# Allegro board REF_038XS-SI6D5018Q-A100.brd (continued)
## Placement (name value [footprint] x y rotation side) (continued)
NOREF#1785  -  []  347.56 144.79 90 top
NOREF#1786  -  []  270.24 240.08 0 top
NOREF#1787  -  []  307.77 233.98 0 top
NOREF#1788  -  []  233.34 210 0 top
NOREF#1789  -  []  228.23 182.08 90 top
NOREF#1790  -  []  274.44 141.43 0 top
NOREF#1791  -  []  270.73 166.09 0 top
NOREF#1792  -  []  485.78 195.82 90 top
NOREF#1793  -  []  82.32 289.93 90 top
NOREF#1794  -  []  348.93 240.74 90 top
NOREF#1795  -  []  311.69 269.1 0 top
NOREF#1796  -  []  307.58 238.18 90 top
NOREF#1797  -  []  450.05 158.1 0 top
NOREF#1798  -  []  210.56 175.55 90 top
NOREF#1799  -  []  331.64 182.3 90 top
NOREF#1800  -  []  334.36 241.55 0 top
NOREF#1801  -  []  232.23 170.19 90 top
NOREF#1802  -  []  335.58 254.86 90 top
NOREF#1803  -  []  286.56 295.33 90 top
NOREF#1804  -  []  210.56 252.32 0 top
NOREF#1805  -  []  273.11 190.18 90 top
NOREF#1806  -  []  100.39 186.2 0 top
NOREF#1807  -  []  271.8 250.18 90 top
NOREF#1808  -  []  475.18 133.72 90 top
NOREF#1809  -  []  242.56 269.73 0 top
NOREF#1810  -  []  254.36 241.55 0 top
NOREF#1811  -  []  285.1 268.22 0 top
NOREF#1812  -  []  265.96 188.86 0 top
NOREF#1813  -  []  356.29 269.73 0 top
NOREF#1814  -  []  110.89 154.45 0 top
NOREF#1815  -  []  122.18 172.97 0 top
NOREF#1816  -  []  212.78 239.12 90 top
NOREF#1817  -  []  347.9 178.48 90 top
NOREF#1818  -  []  243.54 207.24 90 top
NOREF#1819  -  []  90.88 200.91 90 top
NOREF#1820  -  []  254.31 242 90 top
NOREF#1821  -  []  262.63 289.44 0 top
NOREF#1822  -  []  480.6 158.1 0 top
NOREF#1823  -  []  292.96 183.2 0 top
NOREF#1824  -  []  87.69 186.2 0 top
NOREF#1825  -  []  351.08 269.73 0 top
NOREF#1826  -  []  480.05 156.45 0 top
NOREF#1827  -  []  557.76 164.1 90 top
NOREF#1828  -  []  291.33 267.13 0 top
NOREF#1829  -  []  268.25 234.12 90 top
NOREF#1830  -  []  293.39 243.61 0 top
NOREF#1831  -  []  223.09 174.38 0 top
NOREF#1832  -  []  557.76 167.08 0 top
NOREF#1833  -  []  295.16 239.65 90 top
NOREF#1834  -  []  214.36 183.2 0 top
NOREF#1835  -  []  260.33 249.91 0 top
NOREF#1836  -  []  456.32 276.81 90 top
NOREF#1837  -  []  232.79 251.08 0 top
NOREF#1838  -  []  272.23 227.99 0 top
NOREF#1839  -  []  271.54 186.58 0 top
NOREF#1840  -  []  335.01 253.56 90 top
NOREF#1841  -  []  476.65 217.95 0 top
NOREF#1842  -  []  83.29 154.45 0 top
NOREF#1843  -  []  362.64 267.56 0 top
NOREF#1844  -  []  455.4 217.95 0 top
NOREF#1845  -  []  306.06 148.23 0 top
NOREF#1846  -  []  533.93 206.42 0 top
NOREF#1847  -  []  459.8 217.95 0 top
NOREF#1848  -  []  535.51 221.15 90 top
NOREF#1849  -  []  232.46 190.18 90 top
NOREF#1850  -  []  314.91 223.58 90 top
NOREF#1851  -  []  116.75 165.57 90 top
NOREF#1852  -  []  350.54 240.4 0 top
NOREF#1853  -  []  474.45 249.7 0 top
NOREF#1854  -  []  355.37 249.88 90 top
NOREF#1855  -  []  253.09 183.29 90 top
NOREF#1856  -  []  280.81 158.16 0 top
NOREF#1857  -  []  230.91 247.23 90 top
NOREF#1858  -  []  121.88 139.01 0 top
NOREF#1859  -  []  295.58 243.29 90 top
NOREF#1860  -  []  310.55 134.62 90 top
NOREF#1861  -  []  314.73 251.08 0 top
NOREF#1862  -  []  267.56 144.79 0 top
NOREF#1863  -  []  287.56 272.93 0 top
NOREF#1864  -  []  234.61 295.18 90 top
NOREF#1865  -  []  115.04 217.95 0 top
NOREF#1866  -  []  332.66 242 90 top
NOREF#1867  -  []  113.09 217.95 0 top
NOREF#1868  -  []  305.95 248.85 0 top
NOREF#1869  -  []  308.25 233.12 90 top
NOREF#1870  -  []  570 166.3 90 top
NOREF#1871  -  []  225.55 234.13 90 top
NOREF#1872  -  []  254.31 253.56 90 top
NOREF#1873  -  []  290.61 247.17 90 top
NOREF#1874  -  []  307.25 238.48 90 top
NOREF#1875  -  []  333.66 194.76 0 top
NOREF#1876  -  []  456.55 177.57 0 top
NOREF#1877  -  []  570 147.59 90 top
NOREF#1878  -  []  214.66 241.23 0 top
NOREF#1879  -  []  353.66 209.1 90 top
NOREF#1880  -  []  232.74 184.64 90 top
NOREF#1881  -  []  449.05 154.45 0 top
NOREF#1882  -  []  267.9 242.38 90 top
NOREF#1883  -  []  450.05 253.35 0 top
NOREF#1884  -  []  456.64 232.66 0 top
NOREF#1885  -  []  310.83 244.63 0 top
NOREF#1886  -  []  313.66 269.1 90 top
NOREF#1887  -  []  316.94 252.76 90 top
NOREF#1888  -  []  305.05 145.8 0 top
NOREF#1889  -  []  121.88 205.05 0 top
NOREF#1890  -  []  282.34 207.24 0 top
NOREF#1891  -  []  364.49 208.86 0 top
NOREF#1892  -  []  253.99 182.3 90 top
NOREF#1893  -  []  242.24 135.78 90 top
NOREF#1894  -  []  351.54 185.94 90 top
NOREF#1895  -  []  332.01 243.2 0 top
NOREF#1896  -  []  225.06 226.14 0 top
NOREF#1897  -  []  467.84 170.11 90 top
NOREF#1898  -  []  253.99 193.86 90 top
NOREF#1899  -  []  346.92 249.88 90 top
NOREF#1900  -  []  309.83 209.1 90 top
NOREF#1901  -  []  231.49 240.02 0 top
NOREF#1902  -  []  216.33 14.86 90 top
NOREF#1903  -  []  211.16 236.15 90 top
NOREF#1904  -  []  227.59 183.28 0 top
NOREF#1905  -  []  97.24 151.25 90 top
NOREF#1906  -  []  223.27 234.06 0 top
NOREF#1907  -  []  250.56 187.12 90 top
NOREF#1908  -  []  350.24 245.28 0 top
NOREF#1909  -  []  316.65 267.92 0 top
NOREF#1910  -  []  310.54 180.4 0 top
NOREF#1911  -  []  263.27 174.62 0 top
NOREF#1912  -  []  232.46 180.42 90 top
NOREF#1913  -  []  228.27 185.28 0 top
NOREF#1914  -  []  263.71 291.06 0 top
NOREF#1915  -  []  346.93 178.18 90 top
NOREF#1916  -  []  235.38 189.88 90 top
NOREF#1917  -  []  273.63 138.2 0 top
NOREF#1918  -  []  313.11 190.18 90 top
NOREF#1919  -  []  270.89 243.32 0 top
NOREF#1920  -  []  302.22 288.34 90 top
NOREF#1921  -  []  270.5 183.67 90 top
NOREF#1922  -  []  292.01 243.2 0 top
NOREF#1923  -  []  274.91 163.58 0 top
NOREF#1924  -  []  293.39 195.18 0 top
NOREF#1925  -  []  271.19 209.1 90 top
NOREF#1926  -  []  456.4 189.85 0 top
NOREF#1927  -  []  264.52 281.35 90 top
NOREF#1928  -  []  271.19 269.1 90 top
NOREF#1929  -  []  360.04 135.47 90 top
NOREF#1930  -  []  90.64 221.6 0 top
NOREF#1931  -  []  547.34 235.63 0 top
NOREF#1932  -  []  474.25 158.1 0 top
NOREF#1933  -  []  487.64 201.86 90 top
NOREF#1934  -  []  325.29 212.67 0 top
NOREF#1935  -  []  315.44 254.76 90 top
NOREF#1936  -  []  351.15 183.67 90 top
NOREF#1937  -  []  81.69 288.47 90 top
NOREF#1938  -  []  362.34 207.24 0 top
NOREF#1939  -  []  227.05 134.31 90 top
NOREF#1940  -  []  350.57 268.63 0 top
NOREF#1941  -  []  349.59 246.58 0 top
NOREF#1942  -  []  277.95 143.53 90 top
NOREF#1943  -  []  83.67 262.04 90 top
NOREF#1944  -  []  232.14 240.12 90 top
NOREF#1945  -  []  213.1 238.82 90 top
NOREF#1946  -  []  449.05 217.95 0 top
NOREF#1947  -  []  560.13 154.99 0 top
NOREF#1948  -  []  363.24 208.22 90 top
NOREF#1949  -  []  278.32 142.99 0 top
NOREF#1950  -  []  351.54 245.93 90 top
NOREF#1951  -  []  454.65 156.45 0 top
NOREF#1952  -  []  309.85 244.32 90 top
NOREF#1953  -  []  40.05 272.89 0 top
NOREF#1954  -  []  229.59 185.93 0 top
NOREF#1955  -  []  347.58 183.28 0 top
NOREF#1956  -  []  340.66 226.14 0 top
NOREF#1957  -  []  38.35 142.86 0 top
NOREF#1958  -  []  302.63 289.44 0 top
NOREF#1959  -  []  267.25 173.9 90 top
NOREF#1960  -  []  102.38 202.18 0 top
NOREF#1961  -  []  302.86 166.14 0 top
NOREF#1962  -  []  344.52 283.89 90 top
NOREF#1963  -  []  113.09 186.2 0 top
NOREF#1964  -  []  232.46 241.7 0 top
NOREF#1965  -  []  282.56 209.73 0 top
NOREF#1966  -  []  270.57 208.63 0 top
NOREF#1967  -  []  243.54 267.24 90 top
NOREF#1968  -  []  311.16 183.67 90 top
NOREF#1969  -  []  324.79 211.56 0 top
NOREF#1970  -  []  304.96 134.08 0 top
NOREF#1971  -  []  244.35 211.05 90 top
NOREF#1972  -  []  454.65 251.7 0 top
NOREF#1973  -  []  212.66 253.56 90 top
NOREF#1974  -  []  301.62 289.14 90 top
NOREF#1975  -  []  534.23 206.74 0 top
NOREF#1976  -  []  348.23 178.18 90 top
NOREF#1977  -  []  251.64 243.61 0 top
NOREF#1978  -  []  55.09 268.86 0 top
NOREF#1979  -  []  350.73 166.09 90 top
NOREF#1980  -  []  268.27 184.64 90 top
NOREF#1981  -  []  463 214.75 90 top
NOREF#1982  -  []  472.5 154.45 0 top
NOREF#1983  -  []  312.14 180.12 0 top
NOREF#1984  -  []  546.96 196.64 0 top
NOREF#1985  -  []  121.88 236.8 0 top
NOREF#1986  -  []  309.89 246.26 0 top
NOREF#1987  -  []  352.23 227.99 90 top
NOREF#1988  -  []  285.29 212.67 0 top
NOREF#1989  -  []  228.93 240.73 0 top
NOREF#1990  -  []  348.93 208.11 0 top
NOREF#1991  -  []  289.83 263.63 90 top
NOREF#1992  -  []  211.31 194.76 0 top
NOREF#1993  -  []  236.97 208.22 90 top
NOREF#1994  -  []  239.44 140.92 0 top
NOREF#1995  -  []  486.4 219.95 0 top
NOREF#1996  -  []  236.97 268.22 90 top
NOREF#1997  -  []  325.83 169.63 90 top
NOREF#1998  -  []  89.64 154.45 0 top
NOREF#1999  -  []  180.33 2.28 90 top
NOREF#2000  -  []  312.23 170.19 90 top
NOREF#2001  -  []  478.85 154.45 0 top
NOREF#2002  -  []  220.33 249.91 0 top
NOREF#2003  -  []  320.04 135.47 90 top
NOREF#2004  -  []  229.83 209.1 90 top
NOREF#2005  -  []  229.89 246.91 0 top
NOREF#2006  -  []  272.79 183.41 90 top
NOREF#2007  -  []  323.37 273.06 90 top
NOREF#2008  -  []  240.81 218.66 90 top
NOREF#2009  -  []  285.9 272.03 0 top
NOREF#2010  -  []  295.16 191.22 90 top
NOREF#2011  -  []  213.61 253.56 90 top
NOREF#2012  -  []  224.42 175.77 0 top
NOREF#2013  -  []  225.96 188.86 90 top
NOREF#2014  -  []  226.97 246.58 0 top
NOREF#2015  -  []  350.18 191.08 0 top
NOREF#2016  -  []  243.98 207.75 90 top
NOREF#2017  -  []  227.75 235.77 0 top
NOREF#2018  -  []  267.58 238.18 0 top
NOREF#2019  -  []  213.22 178.82 90 top
NOREF#2020  -  []  239.72 136.37 0 top
NOREF#2021  -  []  303.09 234.94 0 top
NOREF#2022  -  []  481.8 221.6 0 top
NOREF#2023  -  []  283.37 213.06 90 top
NOREF#2024  -  []  251.64 183.61 0 top
NOREF#2025  -  []  305.06 166.14 0 top
NOREF#2026  -  []  461 212.35 0 top
NOREF#2027  -  []  225.44 146.16 90 top
NOREF#2028  -  []  286.56 297.26 90 top
NOREF#2029  -  []  309.53 178.82 0 top
NOREF#2030  -  []  102.08 236.8 0 top
NOREF#2031  -  []  333.22 180.02 0 top
NOREF#2032  -  []  214.68 243.61 0 top
NOREF#2033  -  []  270.19 238.82 90 top
NOREF#2034  -  []  546.66 209.66 0 top
NOREF#2035  -  []  310.24 245.28 0 top
NOREF#2036  -  []  292.54 194.86 90 top
NOREF#2037  -  []  49.74 249.91 90 top
NOREF#2038  -  []  456.64 137.41 0 top
NOREF#2039  -  []  102.14 158.1 0 top
NOREF#2040  -  []  211.64 193.86 90 top
NOREF#2041  -  []  95.24 251.7 0 top
NOREF#2042  -  []  37.31 268.86 0 top
NOREF#2043  -  []  481.8 158.1 0 top
NOREF#2044  -  []  474.45 217.95 0 top
NOREF#2045  -  []  78.8 277.9 0 top
NOREF#2046  -  []  253.29 193.86 90 top
NOREF#2047  -  []  297.83 211.13 0 top
NOREF#2048  -  []  292.45 250.39 0 top
NOREF#2049  -  []  468.14 236.47 0 top
NOREF#2050  -  []  317.71 207.75 90 top
NOREF#2051  -  []  282.91 267.92 90 top
NOREF#2052  -  []  354.73 251.08 0 top
NOREF#2053  -  []  485.2 154.45 0 top
NOREF#2054  -  []  305.33 135.72 0 top
NOREF#2055  -  []  323.24 268.22 90 top
NOREF#2056  -  []  456 279.03 90 top
NOREF#2057  -  []  327.4 267.92 90 top
NOREF#2058  -  []  114.29 156.45 0 top
NOREF#2059  -  []  272.13 181.42 90 top
NOREF#2060  -  []  80.94 278.6 0 top
NOREF#2061  -  []  313.4 295.57 0 top
NOREF#2062  -  []  255.83 259.63 0 top
NOREF#2063  -  []  330.56 180.75 0 top
NOREF#2064  -  []  231.16 181.72 90 top
NOREF#2065  -  []  324.79 271.56 0 top
NOREF#2066  -  []  541.25 148.37 0 top
NOREF#2067  -  []  250.61 187.17 90 top
NOREF#2068  -  []  270.5 190.18 90 top
NOREF#2069  -  []  353.4 295.57 0 top
NOREF#2070  -  []  305.88 235.27 0 top
NOREF#2071  -  []  474.45 154.45 0 top
NOREF#2072  -  []  230.5 181.72 90 top
NOREF#2073  -  []  304.52 283.89 90 top
NOREF#2074  -  []  330.56 247.12 90 top
NOREF#2075  -  []  317.14 144.1 90 top
NOREF#2076  -  []  345.48 173.73 90 top
NOREF#2077  -  []  283.15 211.05 0 top
NOREF#2078  -  []  547.04 225.79 0 top
NOREF#2079  -  []  343.27 234.62 0 top
NOREF#2080  -  []  291.96 253.56 90 top
NOREF#2081  -  []  309.53 178.82 90 top
NOREF#2082  -  []  341.62 289.14 90 top
NOREF#2083  -  []  449.05 154.45 0 top
NOREF#2084  -  []  213.22 180.02 0 top
NOREF#2085  -  []  349.59 245.29 90 top
NOREF#2086  -  []  293.54 179.12 90 top
NOREF#2087  -  []  467.84 204.4 90 top
NOREF#2088  -  []  263.27 235.18 0 top
NOREF#2089  -  []  347.77 174.98 0 top
NOREF#2090  -  []  331.34 194.86 0 top
NOREF#2091  -  []  314.78 182.68 0 top
NOREF#2092  -  []  90.79 132.82 0 top
NOREF#2093  -  []  270.57 268.63 90 top
NOREF#2094  -  []  343.71 283.32 90 top
NOREF#2095  -  []  79.1 264.51 0 top
NOREF#2096  -  []  273.66 269.1 90 top
NOREF#2097  -  []  347.94 241.05 0 top
NOREF#2098  -  []  226.29 191.08 0 top
NOREF#2099  -  []  115.04 249.7 0 top
NOREF#2100  -  []  323.98 267.75 90 top
NOREF#2101  -  []  539.45 206.74 90 top
NOREF#2102  -  []  48.35 268.47 0 top
NOREF#2103  -  []  349.23 268.44 0 top
NOREF#2104  -  []  351.48 180.02 0 top
NOREF#2105  -  []  214.36 254.76 0 top
NOREF#2106  -  []  342.22 288.34 90 top
NOREF#2107  -  []  305.48 233.73 90 top
NOREF#2108  -  []  119.44 186.2 0 top
NOREF#2109  -  []  468.14 138.68 0 top
NOREF#2110  -  []  534.23 208.14 0 top
NOREF#2111  -  []  289.83 203.63 90 top
NOREF#2112  -  []  310.57 268.63 90 top
NOREF#2113  -  []  267.64 181.38 0 top
NOREF#2114  -  []  45.61 272.5 0 top
NOREF#2115  -  []  478.85 217.95 0 top
NOREF#2116  -  []  228.01 233.3 90 top
NOREF#2117  -  []  291.34 243.29 0 top
NOREF#2118  -  []  223.09 173.82 0 top
NOREF#2119  -  []  276.97 208.22 90 top
NOREF#2120  -  []  295.71 253.56 90 top
NOREF#2121  -  []  214.68 183.61 0 top
NOREF#2122  -  []  220.66 226.14 0 top
NOREF#2123  -  []  278.83 268.22 0 top
NOREF#2124  -  []  357.14 138.77 90 top
NOREF#2125  -  []  230.84 183.37 0 top
NOREF#2126  -  []  316.07 267.24 0 top
NOREF#2127  -  []  251.16 176.15 90 top
NOREF#2128  -  []  242.57 160.09 0 top
NOREF#2129  -  []  109.42 133.72 90 top
NOREF#2130  -  []  79.1 278.23 0 top
NOREF#2131  -  []  535.51 234.1 90 top
NOREF#2132  -  []  318.39 139.82 90 top
NOREF#2133  -  []  269.59 245.93 90 top
NOREF#2134  -  []  485.2 186.2 0 top
NOREF#2135  -  []  276.47 209.49 0 top
NOREF#2136  -  []  310.82 189.88 90 top
NOREF#2137  -  []  304.96 135.09 0 top
NOREF#2138  -  []  236.23 134 90 top
NOREF#2139  -  []  310.51 239.12 90 top
NOREF#2140  -  []  226.94 238.18 90 top
NOREF#2141  -  []  83.29 249.7 0 top
NOREF#2142  -  []  229.89 246.26 0 top
NOREF#2143  -  []  337.83 271.13 0 top
NOREF#2144  -  []  358.33 268.22 90 top
NOREF#2145  -  []  272.79 191.08 0 top
NOREF#2146  -  []  109.94 246.5 90 top
NOREF#2147  -  []  229.15 210.51 0 top
NOREF#2148  -  []  229.89 185.61 0 top
NOREF#2149  -  []  348.93 181.38 0 top
NOREF#2150  -  []  245.83 229.63 90 top
NOREF#2151  -  []  475.45 221.6 0 top
NOREF#2152  -  []  325.4 272.03 90 top
NOREF#2153  -  []  102.38 233.93 0 top
NOREF#2154  -  []  266.93 238.18 90 top
NOREF#2155  -  []  359.44 136.62 90 top
NOREF#2156  -  []  310.55 134.62 0 top
NOREF#2157  -  []  308.25 234.12 90 top
NOREF#2158  -  []  473.7 251.7 0 top
NOREF#2159  -  []  456.4 253.35 0 top
NOREF#2160  -  []  362.91 267.92 0 top
NOREF#2161  -  []  303.27 234.06 0 top
NOREF#2162  -  []  233.03 294.95 0 top
NOREF#2163  -  []  291.64 183.61 0 top
NOREF#2164  -  []  307.9 178.48 90 top
NOREF#2165  -  []  259.87 207.91 0 top
NOREF#2166  -  []  265.98 245.61 0 top
NOREF#2167  -  []  225.43 295.26 0 top
NOREF#2168  -  []  88.89 188.2 0 top
NOREF#2169  -  []  356.65 207.92 0 top
NOREF#2170  -  []  355.98 182.68 90 top
NOREF#2171  -  []  236.47 209.49 0 top
NOREF#2172  -  []  348.27 185.93 0 top
NOREF#2173  -  []  272.13 243.4 90 top
NOREF#2174  -  []  352.13 240.12 0 top
NOREF#2175  -  []  295.41 295.7 90 top
NOREF#2176  -  []  324.68 274.19 0 top
NOREF#2177  -  []  333.99 193.86 90 top
NOREF#2178  -  []  303.27 174.62 0 top
NOREF#2179  -  []  477.18 160.47 0 top
NOREF#2180  -  []  107.94 148.85 0 top
NOREF#2181  -  []  348.01 173.3 90 top
NOREF#2182  -  []  310.89 183.33 0 top
NOREF#2183  -  []  293.54 190.69 90 top
NOREF#2184  -  []  251.16 191.72 0 top
NOREF#2185  -  []  266.93 189.88 90 top
NOREF#2186  -  []  236.07 207.24 0 top
NOREF#2187  -  []  363.54 207.24 90 top
NOREF#2188  -  []  304.52 290.49 0 top
NOREF#2189  -  []  90.88 202.18 90 top
NOREF#2190  -  []  267.93 247.56 0 top
NOREF#2191  -  []  270.91 187.24 90 top
NOREF#2192  -  []  540.55 206.94 0 top
NOREF#2193  -  []  101.59 180.6 0 top
NOREF#2194  -  []  345.48 233.73 90 top
NOREF#2195  -  []  459.8 249.7 0 top
NOREF#2196  -  []  37.31 266.66 0 top
NOREF#2197  -  []  291.83 170.23 315 top
NOREF#2198  -  []  213.54 190.69 90 top
NOREF#2199  -  []  480.18 202.82 0 top
NOREF#2200  -  []  309.23 240.41 0 top
NOREF#2201  -  []  268.17 137.2 90 top
NOREF#2202  -  []  487.64 138.36 90 top
NOREF#2203  -  []  339.41 166.69 0 top
NOREF#2204  -  []  114.84 189.85 0 top
NOREF#2205  -  []  272.14 240.12 90 top
NOREF#2206  -  []  232.13 183.41 90 top
NOREF#2207  -  []  80 291.62 90 top
NOREF#2208  -  []  121.88 170.11 90 top
NOREF#2209  -  []  268.66 226.14 0 top
NOREF#2210  -  []  350.18 243.37 0 top
NOREF#2211  -  []  108.69 249.7 0 top
NOREF#2212  -  []  270.51 179.12 90 top
NOREF#2213  -  []  308.27 184.64 90 top
NOREF#2214  -  []  310.91 187.24 90 top
NOREF#2215  -  []  294.36 254.76 0 top
NOREF#2216  -  []  541.25 167.08 0 top
NOREF#2217  -  []  294.68 195.18 0 top
NOREF#2218  -  []  456.4 221.6 0 top
NOREF#2219  -  []  293.09 255.5 0 top
NOREF#2220  -  []  315.98 182.68 90 top
NOREF#2221  -  []  293.22 251.59 0 top
NOREF#2222  -  []  219.12 288.34 0 top
NOREF#2223  -  []  240.04 140.12 0 top
NOREF#2224  -  []  355.05 190.18 90 top
NOREF#2225  -  []  315.38 189.88 90 top
NOREF#2226  -  []  459.8 154.45 0 top
NOREF#2227  -  []  232.06 185.29 90 top
NOREF#2228  -  []  549.91 171.11 0 top
NOREF#2229  -  []  233.63 138.2 0 top
NOREF#2230  -  []  107.94 188.2 0 top
NOREF#2231  -  []  114.84 221.6 0 top
NOREF#2232  -  []  470.3 186.2 0 top
NOREF#2233  -  []  271.16 185.61 0 top
NOREF#2234  -  []  357.71 207.75 90 top
NOREF#2235  -  []  354.91 223.58 90 top
NOREF#2236  -  []  350.83 183.37 90 top
NOREF#2237  -  []  268.01 174.3 90 top
NOREF#2238  -  []  332.45 178.82 0 top
NOREF#2239  -  []  95.24 188.2 0 top
NOREF#2240  -  []  478.18 232.07 0 top
NOREF#2241  -  []  351.48 241.42 90 top
NOREF#2242  -  []  487.64 139.01 0 top
NOREF#2243  -  []  534.61 218.68 0 top
NOREF#2244  -  []  480.8 154.45 0 top
NOREF#2245  -  []  263.27 174.06 0 top
NOREF#2246  -  []  362.56 209.73 0 top
NOREF#2247  -  []  255.58 254.86 90 top
NOREF#2248  -  []  245.4 272.03 90 top
NOREF#2249  -  []  482.05 246.5 90 top
NOREF#2250  -  []  230.13 268.11 90 top
NOREF#2251  -  []  305.68 245.29 90 top
NOREF#2252  -  []  352.13 183.41 0 top
NOREF#2253  -  []  310.91 247.88 0 top
NOREF#2254  -  []  292.78 190.69 90 top
NOREF#2255  -  []  268.27 245.28 0 top
NOREF#2256  -  []  102.08 172.65 90 top
NOREF#2257  -  []  364.35 271.05 90 top
NOREF#2258  -  []  264.09 171.46 90 top
NOREF#2259  -  []  487.64 141.55 0 top
NOREF#2260  -  []  475.18 133.72 0 top
NOREF#2261  -  []  310.86 185.29 0 top
NOREF#2262  -  []  366.03 274.19 0 top
NOREF#2263  -  []  308.93 268.11 0 top
NOREF#2264  -  []  330.61 175.6 90 top
NOREF#2265  -  []  228.25 174.12 90 top
NOREF#2266  -  []  227.63 187.24 90 top
NOREF#2267  -  []  283.54 267.24 90 top
NOREF#2268  -  []  230.84 238.82 0 top
NOREF#2269  -  []  316.89 133.69 0 top
NOREF#2270  -  []  358.33 208.22 90 top
NOREF#2271  -  []  543.98 171.11 0 top
NOREF#2272  -  []  456.55 177.57 0 top
NOREF#2273  -  []  80.47 265.74 0 top
NOREF#2274  -  []  303.09 172.9 0 top
NOREF#2275  -  []  292.54 254.86 90 top
NOREF#2276  -  []  89.64 186.2 0 top
NOREF#2277  -  []  345.33 135.72 0 top
NOREF#2278  -  []  272.23 167.99 0 top
NOREF#2279  -  []  313.76 183.65 0 top
NOREF#2280  -  []  541.25 164.88 0 top
NOREF#2281  -  []  65.76 265.88 0 top
NOREF#2282  -  []  306.92 249.88 90 top
NOREF#2283  -  []  343.95 172.9 90 top
NOREF#2284  -  []  311.16 243.67 90 top
NOREF#2285  -  []  230.73 226.09 90 top
NOREF#2286  -  []  230.83 191.08 0 top
NOREF#2287  -  []  266.45 147.01 90 top
NOREF#2288  -  []  57.83 272.89 0 top
NOREF#2289  -  []  307.94 181.06 0 top
NOREF#2290  -  []  311.48 251.08 0 top
NOREF#2291  -  []  349.33 270.27 0 top
NOREF#2292  -  []  480.05 219.95 0 top
NOREF#2293  -  []  498.93 206.36 0 top
NOREF#2294  -  []  226.29 251.08 0 top
NOREF#2295  -  []  486.95 158.1 0 top
NOREF#2296  -  []  251.34 254.86 0 top
NOREF#2297  -  []  214.31 193.56 90 top
NOREF#2298  -  []  349.15 210.51 0 top
NOREF#2299  -  []  315.44 194.76 90 top
NOREF#2300  -  []  226.94 238.18 0 top
NOREF#2301  -  []  255.56 252.47 90 top
NOREF#2302  -  []  350.24 180.08 0 top
NOREF#2303  -  []  286.75 269.12 0 top
NOREF#2304  -  []  312.78 243.4 0 top
NOREF#2305  -  []  345.95 188.86 90 top
NOREF#2306  -  []  272.13 243.4 0 top
NOREF#2307  -  []  227.41 133.69 0 top
NOREF#2308  -  []  309.23 241.06 0 top
NOREF#2309  -  []  267.64 182.03 0 top
NOREF#2310  -  []  224.42 235.77 0 top
NOREF#2311  -  []  365.1 268.22 0 top
NOREF#2312  -  []  345.95 248.85 90 top
NOREF#2313  -  []  227.94 181.06 0 top
NOREF#2314  -  []  64.97 272.5 90 top
NOREF#2315  -  []  79.1 276.97 0 top
NOREF#2316  -  []  229.5 208.8 90 top
NOREF#2317  -  []  535.13 206.42 90 top
NOREF#2318  -  []  350.57 208.63 90 top
NOREF#2319  -  []  478.85 249.7 0 top
NOREF#2320  -  []  308.01 233.3 90 top
NOREF#2321  -  []  543.98 154.6 0 top
NOREF#2322  -  []  467.84 236.15 90 top
NOREF#2323  -  []  456.55 209.32 0 top
NOREF#2324  -  []  294.38 183.29 0 top
NOREF#2325  -  []  310.5 243.67 90 top
NOREF#2326  -  []  360.81 158.16 90 top
NOREF#2327  -  []  259.87 267.91 0 top
NOREF#2328  -  []  84.1 277.6 0 top
NOREF#2329  -  []  316.11 234.13 90 top
NOREF#2330  -  []  307.25 233.9 90 top
NOREF#2331  -  []  255.38 253.86 90 top
NOREF#2332  -  []  95.79 221.6 0 top
NOREF#2333  -  []  230.84 182.62 0 top
NOREF#2334  -  []  498.93 225.77 0 top
NOREF#2335  -  []  268.25 233.12 90 top
NOREF#2336  -  []  83.8 291.64 0 top
NOREF#2337  -  []  227.85 138.1 0 top
NOREF#2338  -  []  253.54 179.12 90 top
NOREF#2339  -  []  226.91 144.24 0 top
NOREF#2340  -  []  299.41 166.69 0 top
NOREF#2341  -  []  351.15 239.12 90 top
NOREF#2342  -  []  238.32 141.41 90 top
NOREF#2343  -  []  323.55 213.3 0 top
NOREF#2344  -  []  286.24 294.36 0 top
NOREF#2345  -  []  226.54 134.31 90 top
NOREF#2346  -  []  353.1 190.18 90 top
NOREF#2347  -  []  351.15 246.26 90 top
NOREF#2348  -  []  265.33 133.69 0 top
NOREF#2349  -  []  78.8 264.19 0 top
NOREF#2350  -  []  267.05 133.3 90 top
NOREF#2351  -  []  333.09 194.86 90 top
NOREF#2352  -  []  560.13 154.21 90 top
NOREF#2353  -  []  229.23 181.06 0 top
NOREF#2354  -  []  457.49 273.15 0 top
NOREF#2355  -  []  267.64 241.38 90 top
NOREF#2356  -  []  235.98 242.68 90 top
NOREF#2357  -  []  317.95 140.86 90 top
NOREF#2358  -  []  211.16 180.15 0 top
NOREF#2359  -  []  307.94 241.7 0 top
NOREF#2360  -  []  268.25 173.12 90 top
NOREF#2361  -  []  311.48 181.42 90 top
NOREF#2362  -  []  284.68 274.19 0 top
NOREF#2363  -  []  480.8 186.2 0 top
NOREF#2364  -  []  233.4 295.57 0 top
NOREF#2365  -  []  103.34 221.6 0 top
NOREF#2366  -  []  310.55 134.62 90 top
NOREF#2367  -  []  349.89 246.91 0 top
NOREF#2368  -  []  265.06 226.14 0 top
NOREF#2369  -  []  350.86 185.29 0 top
NOREF#2370  -  []  83.2 290.32 90 top
NOREF#2371  -  []  312.23 230.19 90 top
NOREF#2372  -  []  461.55 253.35 0 top
NOREF#2373  -  []  357.14 141.43 90 top
NOREF#2374  -  []  78.8 290.36 0 top
NOREF#2375  -  []  539.65 207.34 0 top
NOREF#2376  -  []  232.46 250.18 90 top
NOREF#2377  -  []  478.18 136.82 90 top
NOREF#2378  -  []  547.04 221.6 0 top
NOREF#2379  -  []  305.48 173.73 90 top
NOREF#2380  -  []  236.11 174.13 90 top
NOREF#2381  -  []  275.23 223.88 90 top
NOREF#2382  -  []  264.42 235.77 0 top
NOREF#2383  -  []  252.96 183.2 0 top
NOREF#2384  -  []  280.04 137.42 90 top
NOREF#2385  -  []  217.83 218.13 90 top
NOREF#2386  -  []  316.94 192.76 90 top
NOREF#2387  -  []  55.64 248.1 0 top
NOREF#2388  -  []  549.55 154.21 0 top
NOREF#2389  -  []  310.84 183.37 0 top
NOREF#2390  -  []  237.14 141.43 90 top
NOREF#2391  -  []  365.4 272.03 90 top
NOREF#2392  -  []  344.41 231.76 90 top
NOREF#2393  -  []  367.56 212.93 0 top
NOREF#2394  -  []  367.07 268.22 90 top
NOREF#2395  -  []  307.64 180.73 90 top
NOREF#2396  -  []  237.95 140.86 90 top
NOREF#2397  -  []  293.29 182.3 90 top
NOREF#2398  -  []  237.14 138.77 90 top
NOREF#2399  -  []  83.8 275.82 90 top
NOREF#2400  -  []  291.34 254.86 0 top
NOREF#2401  -  []  346.6 239.75 90 top
NOREF#2402  -  []  269.85 184.32 90 top
NOREF#2403  -  []  242.33 173.13 90 top
NOREF#2404  -  []  329.83 203.63 90 top
NOREF#2405  -  []  331.64 255.18 0 top
NOREF#2406  -  []  121.88 170.76 0 top
NOREF#2407  -  []  234.78 242.68 0 top
NOREF#2408  -  []  309.85 179.12 90 top
NOREF#2409  -  []  230.84 183.37 90 top
NOREF#2410  -  []  308.57 185.61 0 top
NOREF#2411  -  []  312.23 227.99 90 top
NOREF#2412  -  []  347.58 184.06 0 top
NOREF#2413  -  []  311.08 269.73 0 top
NOREF#2414  -  []  312.74 244.64 90 top
NOREF#2415  -  []  228.27 245.29 90 top
NOREF#2416  -  []  334.31 193.56 90 top
NOREF#2417  -  []  246.75 209.12 0 top
NOREF#2418  -  []  224.91 233.9 0 top
NOREF#2419  -  []  265.96 248.85 90 top
NOREF#2420  -  []  252.33 182.3 90 top
NOREF#2421  -  []  271.81 181.72 90 top
NOREF#2422  -  []  500.3 208.83 0 top
NOREF#2423  -  []  333.09 183.93 0 top
NOREF#2424  -  []  455.67 279.93 0 top
NOREF#2425  -  []  234.74 191.08 0 top
NOREF#2426  -  []  353.17 291.16 90 top
NOREF#2427  -  []  223.95 172.9 90 top
NOREF#2428  -  []  348.57 184.96 0 top
NOREF#2429  -  []  310.73 226.09 0 top
NOREF#2430  -  []  455.67 278.73 90 top
NOREF#2431  -  []  292.45 190.39 0 top
NOREF#2432  -  []  475.18 228.97 0 top
NOREF#2433  -  []  271.11 292.69 90 top
NOREF#2434  -  []  267.64 242.02 0 top
NOREF#2435  -  []  254.36 243.2 0 top
NOREF#2436  -  []  487.64 140.9 90 top
NOREF#2437  -  []  284.05 272.03 90 top
NOREF#2438  -  []  233.63 140.86 0 top
NOREF#2439  -  []  294.31 182 90 top
NOREF#2440  -  []  304.96 135.33 0 top
NOREF#2441  -  []  98.19 249.7 0 top
NOREF#2442  -  []  350.24 244.64 90 top
NOREF#2443  -  []  224.41 231.76 90 top
NOREF#2444  -  []  270.54 184.96 0 top
NOREF#2445  -  []  349.59 186.59 90 top
NOREF#2446  -  []  211.96 253.56 90 top
NOREF#2447  -  []  288.21 271.73 90 top
NOREF#2448  -  []  267.58 178.18 0 top
NOREF#2449  -  []  547.34 224.07 0 top
NOREF#2450  -  []  467.9 253.35 0 top
NOREF#2451  -  []  269.5 208.8 0 top
NOREF#2452  -  []  250.61 192.27 0 top
NOREF#2453  -  []  22.44 295.46 90 top
NOREF#2454  -  []  268.27 185.29 90 top
NOREF#2455  -  []  38.32 299.45 0 top
NOREF#2456  -  []  229.59 245.29 90 top
NOREF#2457  -  []  287.07 208.22 90 top
NOREF#2458  -  []  315.12 294.17 90 top
NOREF#2459  -  []  356.52 133.3 90 top
NOREF#2460  -  []  211.34 243.29 0 top
NOREF#2461  -  []  272.14 182.07 0 top
NOREF#2462  -  []  270.5 243.67 90 top
NOREF#2463  -  []  273.17 291.16 90 top
NOREF#2464  -  []  273.11 243.7 90 top
NOREF#2465  -  []  467.35 148.85 0 top
NOREF#2466  -  []  463 183 90 top
NOREF#2467  -  []  311.54 185.94 90 top
NOREF#2468  -  []  291.83 263.63 0 top
NOREF#2469  -  []  346.6 179.76 90 top
NOREF#2470  -  []  227.77 233.98 0 top
NOREF#2471  -  []  308.93 180.09 90 top
NOREF#2472  -  []  234.91 163.58 90 top
NOREF#2473  -  []  335.01 193.56 90 top
NOREF#2474  -  []  113.09 249.7 0 top
NOREF#2475  -  []  347.64 241.38 90 top
NOREF#2476  -  []  360.81 218.66 90 top
NOREF#2477  -  []  568.79 166.69 0 top
NOREF#2478  -  []  37.86 250.3 0 top
NOREF#2479  -  []  293.22 240.02 0 top
NOREF#2480  -  []  350.13 268.11 90 top
NOREF#2481  -  []  83.8 277.93 0 top
NOREF#2482  -  []  346.74 294.64 0 top
NOREF#2483  -  []  283.45 271.37 0 top
NOREF#2484  -  []  291.16 187.72 90 top
NOREF#2485  -  []  472.5 186.2 0 top
NOREF#2486  -  []  117.42 223.97 90 top
NOREF#2487  -  []  343.71 288.65 90 top
NOREF#2488  -  []  314.44 138.77 0 top
NOREF#2489  -  []  213.22 250.39 90 top
NOREF#2490  -  []  242.91 207.92 90 top
NOREF#2491  -  []  271.54 245.93 90 top
NOREF#2492  -  []  486.4 212.35 0 top
NOREF#2493  -  []  83.29 186.2 0 top
NOREF#2494  -  []  213.09 183.93 0 top
NOREF#2495  -  []  90.79 196.32 90 top
NOREF#2496  -  []  307.93 247.56 0 top
NOREF#2497  -  []  551.91 149.79 0 top
NOREF#2498  -  []  211.64 243.61 0 top
NOREF#2499  -  []  269.23 241.06 0 top
NOREF#2500  -  []  469.1 221.6 0 top
NOREF#2501  -  []  316.29 269.73 0 top
NOREF#2502  -  []  80 264.19 90 top
NOREF#2503  -  []  348.93 180.09 90 top
NOREF#2504  -  []  293.99 242.3 90 top
NOREF#2505  -  []  310.18 191.08 0 top
NOREF#2506  -  []  355.6 281.03 90 top
NOREF#2507  -  []  292.54 243.29 90 top
NOREF#2508  -  []  211.31 243.2 0 top
NOREF#2509  -  []  243.45 211.37 0 top
NOREF#2510  -  []  215.58 194.86 90 top
NOREF#2511  -  []  210.61 247.17 90 top
NOREF#2512  -  []  303.71 280.78 90 top
NOREF#2513  -  []  350.83 178.82 90 top
NOREF#2514  -  []  228.57 185.61 0 top
NOREF#2515  -  []  347.77 233.98 0 top
NOREF#2516  -  []  488.4 246.5 90 top
NOREF#2517  -  []  295.06 183.2 0 top
NOREF#2518  -  []  343.34 286.27 90 top
NOREF#2519  -  []  242.56 209.73 0 top
NOREF#2520  -  []  223.27 174.62 0 top
NOREF#2521  -  []  307.25 174.3 90 top
NOREF#2522  -  []  291.34 183.29 0 top
NOREF#2523  -  []  345.68 245.29 90 top
NOREF#2524  -  []  485.78 132.32 90 top
NOREF#2525  -  []  293.09 195.5 0 top
NOREF#2526  -  []  232.2 284.47 0 top
NOREF#2527  -  []  275.06 190.18 90 top
NOREF#2528  -  []  230.18 183.37 0 top
NOREF#2529  -  []  283.37 273.06 90 top
NOREF#2530  -  []  88.89 212.35 0 top
NOREF#2531  -  []  347.25 174.3 90 top
NOREF#2532  -  []  229.86 244.32 90 top
NOREF#2533  -  []  311.47 249.88 90 top
NOREF#2534  -  []  219.42 293.48 0 top
NOREF#2535  -  []  263.95 174.94 90 top
NOREF#2536  -  []  468.14 204.72 0 top
NOREF#2537  -  []  245.83 169.63 90 top
NOREF#2538  -  []  352.78 249.88 90 top
NOREF#2539  -  []  233.49 291.46 90 top
NOREF#2540  -  []  451.25 217.95 0 top
NOREF#2541  -  []  316.37 267.56 0 top
NOREF#2542  -  []  294.68 255.18 0 top
NOREF#2543  -  []  102.38 204.72 0 top
NOREF#2544  -  []  475.18 228.97 90 top
NOREF#2545  -  []  164 132.9 90 top
NOREF#2546  -  []  89.44 221.6 0 top
NOREF#2547  -  []  314.91 223.58 0 top
NOREF#2548  -  []  211.33 207.13 0 top
NOREF#2549  -  []  230.57 268.63 90 top
NOREF#2550  -  []  294.36 253.12 0 top
NOREF#2551  -  []  353.35 181.38 90 top
NOREF#2552  -  []  238.71 140.12 90 top
NOREF#2553  -  []  273.76 183.65 0 top
NOREF#2554  -  []  243.37 273.54 0 top
NOREF#2555  -  []  270.89 242.68 90 top
NOREF#2556  -  []  235.12 294.17 0 top
NOREF#2557  -  []  229.89 245.61 0 top
NOREF#2558  -  []  103.34 189.85 0 top
NOREF#2559  -  []  342.86 166.14 0 top
NOREF#2560  -  []  358.22 208.86 0 top
NOREF#2561  -  []  347.9 184.36 90 top
NOREF#2562  -  []  253.22 250.39 90 top
NOREF#2563  -  []  225.96 248.85 0 top
NOREF#2564  -  []  234.91 163.58 0 top
NOREF#2565  -  []  352.78 183.41 0 top
NOREF#2566  -  []  276.29 269.25 90 top
NOREF#2567  -  []  353.1 243.7 90 top
NOREF#2568  -  []  231.21 247.56 0 top
NOREF#2569  -  []  267.9 184.36 90 top
NOREF#2570  -  []  270.84 187.16 0 top
NOREF#2571  -  []  339.72 293.16 0 top
NOREF#2572  -  []  345.95 248.85 0 top
NOREF#2573  -  []  225.33 134.7 0 top
NOREF#2574  -  []  291.31 194.76 0 top
NOREF#2575  -  []  454.65 212.35 0 top
NOREF#2576  -  []  112.42 232.07 0 top
NOREF#2577  -  []  63.76 272.89 0 top
NOREF#2578  -  []  308.55 238.48 90 top
NOREF#2579  -  []  322.33 233.13 90 top
NOREF#2580  -  []  225.48 173.73 90 top
NOREF#2581  -  []  90.79 164.57 0 top
NOREF#2582  -  []  227.59 178.18 0 top
NOREF#2583  -  []  235.44 254.76 90 top
NOREF#2584  -  []  360.48 209.12 0 top
NOREF#2585  -  []  350.5 181.72 90 top
NOREF#2586  -  []  348.27 245.28 0 top
NOREF#2587  -  []  340.66 166.14 0 top
NOREF#2588  -  []  114.42 139.32 0 top
NOREF#2589  -  []  270.55 134.62 90 top
NOREF#2590  -  []  214.66 192.79 0 top
NOREF#2591  -  []  307.63 187.24 90 top
NOREF#2592  -  []  37.49 248.49 0 top
NOREF#2593  -  []  270.89 183.33 0 top
NOREF#2594  -  []  470.3 217.95 0 top
NOREF#2595  -  []  116.75 229.07 90 top
NOREF#2596  -  []  229.23 240.41 0 top
NOREF#2597  -  []  295.16 179.65 90 top
NOREF#2598  -  []  323.15 271.05 0 top
NOREF#2599  -  []  114.29 219.95 0 top
NOREF#2600  -  []  237.71 207.75 90 top
NOREF#2601  -  []  266.28 251.08 0 top
NOREF#2602  -  []  363.37 213.54 0 top
NOREF#2603  -  []  363.83 218.13 90 top
NOREF#2604  -  []  109.42 197.22 90 top
NOREF#2605  -  []  547.04 235.95 0 top
NOREF#2606  -  []  234.44 144.1 0 top
NOREF#2607  -  []  314.73 191.08 0 top
NOREF#2608  -  []  252.01 183.2 0 top
NOREF#2609  -  []  57.46 272.5 90 top
NOREF#2610  -  []  285.58 213.87 90 top
NOREF#2611  -  []  230.89 243.32 0 top
NOREF#2612  -  []  241.34 136.1 0 top
NOREF#2613  -  []  223.71 280.78 90 top
NOREF#2614  -  []  282.33 233.13 90 top
NOREF#2615  -  []  49.56 265.88 90 top
NOREF#2616  -  []  350.83 183.37 0 top
NOREF#2617  -  []  304.52 287.83 0 top
NOREF#2618  -  []  108.65 227.5 0 top
NOREF#2619  -  []  273.46 243.33 0 top
NOREF#2620  -  []  333.29 193.86 90 top
NOREF#2621  -  []  415.96 132.9 90 top
NOREF#2622  -  []  275.48 293.54 0 top
NOREF#2623  -  []  233.66 209.1 90 top
NOREF#2624  -  []  93.31 162.36 0 top
NOREF#2625  -  []  330.61 240.7 0 top
NOREF#2626  -  []  229.33 270.27 0 top
NOREF#2627  -  []  238.83 208.22 0 top
NOREF#2628  -  []  295.06 243.2 0 top
NOREF#2629  -  []  273.63 140.86 0 top
NOREF#2630  -  []  265.96 188.86 0 top
NOREF#2631  -  []  487.94 170.43 0 top
NOREF#2632  -  []  311.19 243 0 top
NOREF#2633  -  []  343.09 234.94 0 top
NOREF#2634  -  []  267.58 244.06 0 top
NOREF#2635  -  []  267.58 238.18 90 top
NOREF#2636  -  []  307.58 243.28 0 top
NOREF#2637  -  []  271.11 293.99 90 top
NOREF#2638  -  []  59.94 142.86 0 top
NOREF#2639  -  []  337.83 211.13 0 top
NOREF#2640  -  []  96.99 253.35 0 top
NOREF#2641  -  []  253.54 250.69 90 top
NOREF#2642  -  []  248.21 211.73 90 top
NOREF#2643  -  []  277.71 267.75 0 top
NOREF#2644  -  []  309.53 184.02 90 top
NOREF#2645  -  []  269.5 268.8 90 top
NOREF#2646  -  []  103.34 253.35 0 top
NOREF#2647  -  []  343.95 173.82 90 top
NOREF#2648  -  []  251.31 183.2 0 top
NOREF#2649  -  []  461.07 165.72 90 top
NOREF#2650  -  []  236.52 133.3 90 top
NOREF#2651  -  []  520.71 146.13 90 top
NOREF#2652  -  []  306.6 239.75 90 top
NOREF#2653  -  []  334.38 183.29 0 top
NOREF#2654  -  []  260.67 289.14 0 top
NOREF#2655  -  []  269.89 245.61 0 top
NOREF#2656  -  []  401.33 417.57 90 top
NOREF#2657  -  []  353.63 143.53 0 top
NOREF#2658  -  []  38.35 169.53 0 top
NOREF#2659  -  []  229.59 246.58 0 top
NOREF#2660  -  []  312.14 240.12 0 top
NOREF#2661  -  []  214.68 182.3 90 top
NOREF#2662  -  []  352.23 227.99 0 top
NOREF#2663  -  []  293.66 254.76 0 top
NOREF#2664  -  []  39.68 273.28 0 top
NOREF#2665  -  []  355.83 283.46 0 top
NOREF#2666  -  []  88.89 251.7 0 top
NOREF#2667  -  []  312.23 172.39 90 top
NOREF#2668  -  []  356.65 207.92 90 top
NOREF#2669  -  []  351.47 189.88 90 top
NOREF#2670  -  []  348.26 222.94 90 top
NOREF#2671  -  []  323.15 211.05 0 top
NOREF#2672  -  []  254.68 182.3 90 top
NOREF#2673  -  []  121.88 173.3 0 top
NOREF#2674  -  []  277.71 207.75 0 top
NOREF#2675  -  []  270.91 247.88 0 top
NOREF#2676  -  []  232.23 172.39 90 top
NOREF#2677  -  []  473.7 156.45 0 top
NOREF#2678  -  []  273.63 143.53 0 top
NOREF#2679  -  []  83.2 276.6 90 top
NOREF#2680  -  []  547.34 237.02 0 top
NOREF#2681  -  []  310.82 241.42 90 top
NOREF#2682  -  []  456.55 164.57 90 top
NOREF#2683  -  []  260.33 189.91 0 top
NOREF#2684  -  []  109.69 189.85 0 top
NOREF#2685  -  []  254.66 181.23 0 top
NOREF#2686  -  []  343.71 283.19 0 top
NOREF#2687  -  []  249.83 203.63 90 top
NOREF#2688  -  []  363.37 273.06 90 top
NOREF#2689  -  []  294.68 182.3 90 top
NOREF#2690  -  []  348.93 268.11 0 top
NOREF#2691  -  []  329.83 263.63 90 top
NOREF#2692  -  []  451.25 154.45 0 top
NOREF#2693  -  []  315.12 293.93 0 top
NOREF#2694  -  []  271.08 269.73 0 top
NOREF#2695  -  []  80 290.36 90 top
NOREF#2696  -  []  65.94 247.71 0 top
NOREF#2697  -  []  234.61 294.17 90 top
NOREF#2698  -  []  262.95 288.54 90 top
NOREF#2699  -  []  90.89 246.5 90 top
NOREF#2700  -  []  10.78 2.28 90 top
NOREF#2701  -  []  535.13 205.02 90 top
NOREF#2702  -  []  230.91 247.88 0 top
NOREF#2703  -  []  94.04 217.95 0 top
NOREF#2704  -  []  275.38 249.88 90 top
NOREF#2705  -  []  299.33 196.13 0 top
NOREF#2706  -  []  294.68 243.61 0 top
NOREF#2707  -  []  230.83 244.63 0 top
NOREF#2708  -  []  547.34 221.28 0 top
NOREF#2709  -  []  326.75 209.12 0 top
NOREF#2710  -  []  267.94 181.7 0 top
NOREF#2711  -  []  263.95 234.94 90 top
NOREF#2712  -  []  352.78 243.4 0 top
NOREF#2713  -  []  339.42 292.84 90 top
NOREF#2714  -  []  102.38 172.97 0 top
NOREF#2715  -  []  217.83 222.13 90 top
NOREF#2716  -  []  226.97 186.58 0 top
NOREF#2717  -  []  250.56 240.75 0 top
NOREF#2718  -  []  242.56 269.25 90 top
NOREF#2719  -  []  229.59 185.29 90 top
NOREF#2720  -  []  241.52 238.62 0 top
NOREF#2721  -  []  210.61 240.7 0 top
NOREF#2722  -  []  352.13 243.4 0 top
NOREF#2723  -  []  312.13 238.82 90 top
NOREF#2724  -  []  478.68 175.62 0 top
NOREF#2725  -  []  227.77 173.98 0 top
NOREF#2726  -  []  367.4 267.92 90 top
NOREF#2727  -  []  354.44 141.43 0 top
NOREF#2728  -  []  327.56 272.93 0 top
NOREF#2729  -  []  290.56 180.75 0 top
NOREF#2730  -  []  228.93 241.38 0 top
NOREF#2731  -  []  351.69 269.1 0 top
NOREF#2732  -  []  249.83 203.63 90 top
NOREF#2733  -  []  290.56 235.55 90 top
NOREF#2734  -  []  270.84 183.37 0 top
NOREF#2735  -  []  322.91 207.92 90 top
NOREF#2736  -  []  456.64 200.91 0 top
NOREF#2737  -  []  271.69 269.1 0 top
NOREF#2738  -  []  294.31 193.56 90 top
NOREF#2739  -  []  303.71 288.4 0 top
NOREF#2740  -  []  350.73 166.09 0 top
NOREF#2741  -  []  485.78 164.07 90 top
NOREF#2742  -  []  500.3 226.99 0 top
NOREF#2743  -  []  211.64 195.18 0 top
NOREF#2744  -  []  324.05 212.03 90 top
NOREF#2745  -  []  115.81 278.82 0 top
NOREF#2746  -  []  339.33 196.13 0 top
NOREF#2747  -  []  225.48 175.27 0 top
NOREF#2748  -  []  80 276.65 90 top
NOREF#2749  -  []  270.24 185.28 0 top
NOREF#2750  -  []  291.16 180.15 0 top
NOREF#2751  -  []  355.48 293.54 0 top
NOREF#2752  -  []  475.18 165.47 90 top
NOREF#2753  -  []  356.29 269.25 90 top
NOREF#2754  -  []  350.82 189.88 90 top
NOREF#2755  -  []  227.64 240.73 90 top
NOREF#2756  -  []  333.39 195.18 0 top
NOREF#2757  -  []  455.2 253.35 0 top
NOREF#2758  -  []  473.7 148.85 0 top
NOREF#2759  -  []  309.5 208.8 0 top
NOREF#2760  -  []  568.79 147.98 0 top
NOREF#2761  -  []  39.86 299.18 0 top
NOREF#2762  -  []  95.99 249.7 0 top
NOREF#2763  -  []  275.38 189.88 90 top
NOREF#2764  -  []  269.89 185.61 0 top
NOREF#2765  -  []  227.56 144.79 0 top
NOREF#2766  -  []  334.68 243.61 0 top
NOREF#2767  -  []  230.54 180.4 0 top
NOREF#2768  -  []  255.83 199.63 0 top
NOREF#2769  -  []  234.74 251.08 0 top
NOREF#2770  -  []  469.1 158.1 0 top
NOREF#2771  -  []  364.35 211.05 90 top
NOREF#2772  -  []  307.64 182.03 0 top
NOREF#2773  -  []  307.05 134.31 90 top
NOREF#2774  -  []  455.4 249.7 0 top
NOREF#2775  -  []  348.27 245.29 90 top
NOREF#2776  -  []  229.86 184.32 90 top
NOREF#2777  -  []  227.25 173.9 90 top
NOREF#2778  -  []  55.09 268.08 90 top
NOREF#2779  -  []  317.14 146.64 90 top
NOREF#2780  -  []  487.94 233.93 0 top
NOREF#2781  -  []  342.96 225.63 90 top
NOREF#2782  -  []  284.49 268.86 0 top
NOREF#2783  -  []  228.57 245.61 0 top
NOREF#2784  -  []  483.18 223.97 90 top
NOREF#2785  -  []  272.16 181.38 0 top
NOREF#2786  -  []  231.54 186.58 0 top
NOREF#2787  -  []  90.89 183 90 top
NOREF#2788  -  []  547.04 225.14 90 top
NOREF#2789  -  []  339.12 288.34 0 top
NOREF#2790  -  []  291.16 236.15 90 top
NOREF#2791  -  []  307.25 173.9 90 top
NOREF#2792  -  []  235.06 190.18 90 top
NOREF#2793  -  []  328.21 211.73 90 top
NOREF#2794  -  []  547.04 234.56 0 top
NOREF#2795  -  []  303.95 173.82 90 top
NOREF#2796  -  []  291.31 183.2 0 top
NOREF#2797  -  []  267.75 175.77 0 top
NOREF#2798  -  []  457.6 154.45 0 top
NOREF#2799  -  []  252.01 243.2 0 top
NOREF#2800  -  []  333.61 242 90 top
NOREF#2801  -  []  281.13 207.92 90 top
NOREF#2802  -  []  330.33 222.13 90 top
NOREF#2803  -  []  275.06 250.18 90 top
NOREF#2804  -  []  254.68 195.18 0 top
NOREF#2805  -  []  269.59 185.93 0 top
NOREF#2806  -  []  270.18 242.62 0 top
NOREF#2807  -  []  318.83 268.22 0 top
NOREF#2808  -  []  227.91 184.36 90 top
NOREF#2809  -  []  102.08 139.01 0 top
NOREF#2810  -  []  330.56 187.12 90 top
NOREF#2811  -  []  486.4 180.6 0 top
NOREF#2812  -  []  362.24 135.78 90 top
NOREF#2813  -  []  449.05 249.7 0 top
NOREF#2814  -  []  316.97 208.22 90 top
NOREF#2815  -  []  343.09 172.9 0 top
NOREF#2816  -  []  327.88 212.03 90 top
NOREF#2817  -  []  231.48 245.96 90 top
NOREF#2818  -  []  212.78 179.12 90 top
NOREF#2819  -  []  300.67 289.14 0 top
NOREF#2820  -  []  230.83 251.08 0 top
NOREF#2821  -  []  272.45 183.7 90 top
NOREF#2822  -  []  245.73 274.51 0 top
NOREF#2823  -  []  55.46 266.27 0 top
NOREF#2824  -  []  457.19 272.83 90 top
NOREF#2825  -  []  480.05 212.35 0 top
NOREF#2826  -  []  223.95 174.94 90 top
NOREF#2827  -  []  91.84 186.2 0 top
NOREF#2828  -  []  543.62 170.72 90 top
NOREF#2829  -  []  306.93 238.18 0 top
NOREF#2830  -  []  534.61 221.48 0 top
NOREF#2831  -  []  351.19 269.1 90 top
NOREF#2832  -  []  308.44 262.36 0 top
NOREF#2833  -  []  90.88 200.91 0 top
NOREF#2834  -  []  287.65 220.09 90 top
NOREF#2835  -  []  459.07 194.11 0 top
NOREF#2836  -  []  90.79 177.57 0 top
NOREF#2837  -  []  108.49 158.1 0 top
NOREF#2838  -  []  80.94 292.32 0 top
NOREF#2839  -  []  273.36 241.38 90 top
NOREF#2840  -  []  236.29 209.73 0 top
NOREF#2841  -  []  89.64 186.2 0 top
NOREF#2842  -  []  286.24 295.03 0 top
NOREF#2843  -  []  212.01 243.2 0 top
NOREF#2844  -  []  277.14 138.77 90 top
NOREF#2845  -  []  475.45 158.1 0 top
NOREF#2846  -  []  277.95 140.86 90 top
NOREF#2847  -  []  82.01 260.74 90 top
NOREF#2848  -  []  223.09 174.94 0 top
NOREF#2849  -  []  213.66 243.2 0 top
NOREF#2850  -  []  347.94 241.7 0 top
NOREF#2851  -  []  353.42 249.88 90 top
NOREF#2852  -  []  275.98 182.68 90 top
NOREF#2853  -  []  299.41 226.69 0 top
NOREF#2854  -  []  319.44 140.92 0 top
NOREF#2855  -  []  553.49 147.59 90 top
NOREF#2856  -  []  83.8 263.56 90 top
NOREF#2857  -  []  232.79 191.08 0 top
NOREF#2858  -  []  55.64 250.3 0 top
NOREF#2859  -  []  223.95 232.9 90 top
NOREF#2860  -  []  232.13 178.82 90 top
NOREF#2861  -  []  365.29 212.67 0 top
NOREF#2862  -  []  355.08 243 0 top
NOREF#2863  -  []  307.41 134.7 0 top
NOREF#2864  -  []  316.97 268.22 90 top
NOREF#2865  -  []  292.33 242.3 90 top
NOREF#2866  -  []  343.27 174.62 0 top
NOREF#2867  -  []  280.81 218.16 0 top
NOREF#2868  -  []  270.18 243.37 90 top
NOREF#2869  -  []  80.47 293.17 0 top
NOREF#2870  -  []  332.45 238.82 0 top
NOREF#2871  -  []  467.84 140.9 90 top
NOREF#2872  -  []  347.77 173.98 0 top
NOREF#2873  -  []  245.58 213.87 90 top
NOREF#2874  -  []  305.98 245.61 0 top
NOREF#2875  -  []  251.83 263.63 0 top
NOREF#2876  -  []  223.27 288.24 90 top
NOREF#2877  -  []  312.14 242.07 90 top
NOREF#2878  -  []  269.5 268.8 0 top
NOREF#2879  -  []  83.8 265.01 90 top
NOREF#2880  -  []  284.6 208.22 90 top
NOREF#2881  -  []  90.64 189.85 0 top
NOREF#2882  -  []  316.07 207.24 0 top
NOREF#2883  -  []  357.71 267.75 90 top
NOREF#2884  -  []  328.21 271.73 90 top
NOREF#2885  -  []  236.29 269.73 0 top
NOREF#2886  -  []  269.89 246.26 0 top
NOREF#2887  -  []  230.84 178.82 0 top
NOREF#2888  -  []  245.73 214.51 0 top
NOREF#2889  -  []  269.23 268.44 0 top
NOREF#2890  -  []  222.96 225.63 90 top
NOREF#2891  -  []  224.52 290.49 0 top
NOREF#2892  -  []  469.35 183 90 top
NOREF#2893  -  []  331.64 253.86 90 top
NOREF#2894  -  []  295.56 180.9 90 top
NOREF#2895  -  []  307.64 241.38 90 top
NOREF#2896  -  []  293.1 250.39 90 top
NOREF#2897  -  []  276.23 223.88 90 top
NOREF#2898  -  []  228.27 185.29 90 top
NOREF#2899  -  []  228.17 137.2 90 top
NOREF#2900  -  []  255.16 191.22 90 top
NOREF#2901  -  []  557.76 150.57 0 top
NOREF#2902  -  []  214.68 195.18 0 top
NOREF#2903  -  []  57.64 255.11 0 top
NOREF#2904  -  []  227.25 233.9 90 top
NOREF#2905  -  []  551.12 170.72 90 top
NOREF#2906  -  []  275.98 242.68 90 top
NOREF#2907  -  []  318.22 268.86 0 top
NOREF#2908  -  []  501.84 203.84 90 top
NOREF#2909  -  []  540.94 233.23 0 top
NOREF#2910  -  []  230.83 249.88 90 top
NOREF#2911  -  []  226.54 133.3 90 top
NOREF#2912  -  []  276.11 174.13 90 top
NOREF#2913  -  []  364.38 273.87 0 top
NOREF#2914  -  []  287.56 212.93 0 top
NOREF#2915  -  []  252.96 254.76 0 top
NOREF#2916  -  []  480.05 148.85 0 top
NOREF#2917  -  []  333.22 191.59 0 top
NOREF#2918  -  []  215.01 193.56 90 top
NOREF#2919  -  []  66.31 250.3 0 top
NOREF#2920  -  []  270.84 178.82 0 top
NOREF#2921  -  []  215.56 192.47 90 top
NOREF#2922  -  []  264.96 135.33 0 top
NOREF#2923  -  []  90.89 151.25 90 top
NOREF#2924  -  []  480.05 251.7 0 top
NOREF#2925  -  []  95.99 154.45 0 top
NOREF#2926  -  []  236.65 207.92 90 top
NOREF#2927  -  []  267.63 187.88 0 top
NOREF#2928  -  []  90.79 241.07 0 top
NOREF#2929  -  []  307.64 242.02 0 top
NOREF#2930  -  []  253.09 195.5 0 top
NOREF#2931  -  []  290.56 187.12 90 top
NOREF#2932  -  []  227.25 174.3 90 top
NOREF#2933  -  []  116.04 221.6 0 top
NOREF#2934  -  []  465.17 277.78 90 top
NOREF#2935  -  []  488.4 183 90 top
NOREF#2936  -  []  307.64 240.73 90 top
NOREF#2937  -  []  363.72 271.73 0 top
NOREF#2938  -  []  235.12 293.93 0 top
NOREF#2939  -  []  276.07 267.24 0 top
NOREF#2940  -  []  541.95 196.24 90 top
NOREF#2941  -  []  330.61 235.6 90 top
NOREF#2942  -  []  346.06 148.23 0 top
NOREF#2943  -  []  349.23 208.44 0 top
NOREF#2944  -  []  249.83 263.63 90 top
NOREF#2945  -  []  232.14 240.12 0 top
NOREF#2946  -  []  311.54 186.58 0 top
NOREF#2947  -  []  300.33 249.91 0 top
NOREF#2948  -  []  312.14 251.08 0 top
NOREF#2949  -  []  535.13 209.21 90 top
NOREF#2950  -  []  45.79 254.33 0 top
NOREF#2951  -  []  213.22 240.02 0 top
NOREF#2952  -  []  97.24 214.75 90 top
NOREF#2953  -  []  350.91 247.23 90 top
NOREF#2954  -  []  312.78 251.08 0 top
NOREF#2955  -  []  225.98 245.61 0 top
NOREF#2956  -  []  467.35 219.95 0 top
NOREF#2957  -  []  279.44 136.62 90 top
NOREF#2958  -  []  230.51 239.12 90 top
NOREF#2959  -  []  90.88 138.68 90 top
NOREF#2960  -  []  253.39 243.61 0 top
NOREF#2961  -  []  89.44 253.35 0 top
NOREF#2962  -  []  351.48 245.96 90 top
NOREF#2963  -  []  293.1 238.82 90 top
NOREF#2964  -  []  312.46 240.42 90 top
NOREF#2965  -  []  228.01 234.3 90 top
NOREF#2966  -  []  263.71 285.98 90 top
NOREF#2967  -  []  212.01 194.76 0 top
NOREF#2968  -  []  231.19 209.1 90 top
NOREF#2969  -  []  308.26 162.94 90 top
NOREF#2970  -  []  251.31 254.76 0 top
NOREF#2971  -  []  47.98 265.88 0 top
NOREF#2972  -  []  343.95 233.82 90 top
NOREF#2973  -  []  273.4 295.57 0 top
NOREF#2974  -  []  552.28 164.49 0 top
NOREF#2975  -  []  224.96 135.33 90 top
NOREF#2976  -  []  301.62 293.19 90 top
NOREF#2977  -  []  228.24 238.18 90 top
NOREF#2978  -  []  350.24 184.64 90 top
NOREF#2979  -  []  237.95 138.2 90 top
NOREF#2980  -  []  363.45 271.37 0 top
NOREF#2981  -  []  270.24 245.28 0 top
NOREF#2982  -  []  90.88 169.16 0 top
NOREF#2983  -  []  305.42 2.28 90 top
NOREF#2984  -  []  274.1 283.17 90 top
NOREF#2985  -  []  251.83 170.23 315 top
NOREF#2986  -  []  316.29 269.25 90 top
NOREF#2987  -  []  365.58 213.87 90 top
NOREF#2988  -  []  231.69 269.1 0 top
NOREF#2989  -  []  316.11 174.13 90 top
NOREF#2990  -  []  323.45 211.37 0 top
NOREF#2991  -  []  283.98 207.75 0 top
NOREF#2992  -  []  468.14 202.18 0 top
NOREF#2993  -  []  299.41 226.69 0 top
NOREF#2994  -  []  255.56 240.9 90 top
NOREF#2995  -  []  262.86 226.14 0 top
NOREF#2996  -  []  364.38 213.87 0 top
NOREF#2997  -  []  541.25 166.3 90 top
NOREF#2998  -  []  272.23 167.99 90 top
NOREF#2999  -  []  365.58 273.87 90 top
NOREF#3000  -  []  308.49 136.9 90 top
NOREF#3001  -  []  325.73 274.51 0 top
NOREF#3002  -  []  227.93 187.56 0 top
NOREF#3003  -  []  226.61 250.18 90 top
NOREF#3004  -  []  309.59 247.23 0 top
NOREF#3005  -  []  503.94 226.59 0 top
NOREF#3006  -  []  291.96 242 90 top
NOREF#3007  -  []  275.83 281.88 90 top
NOREF#3008  -  []  285.73 273.87 90 top
NOREF#3009  -  []  316.23 223.88 90 top
NOREF#3010  -  []  547.04 224.4 0 top
NOREF#3011  -  []  108.69 249.7 0 top
NOREF#3012  -  []  275.48 295.57 0 top
NOREF#3013  -  []  219.41 166.69 0 top
NOREF#3014  -  []  108.69 186.2 0 top
NOREF#3015  -  []  268.55 178.48 90 top
NOREF#3016  -  []  283.98 207.75 90 top
NOREF#3017  -  []  251.96 242 90 top
NOREF#3018  -  []  307.58 183.28 0 top
NOREF#3019  -  []  353.66 269.1 90 top
NOREF#3020  -  []  331.64 243.61 0 top
NOREF#3021  -  []  349.23 240.41 0 top
NOREF#3022  -  []  219.42 292.84 90 top
NOREF#3023  -  []  231.49 180.02 0 top
NOREF#3024  -  []  331.31 254.76 0 top
NOREF#3025  -  []  351.48 185.96 90 top
NOREF#3026  -  []  350.51 239.12 90 top
NOREF#3027  -  []  274.61 295.18 90 top
NOREF#3028  -  []  334.68 242.3 90 top
NOREF#3029  -  []  461 251.7 0 top
NOREF#3030  -  []  358.83 208.22 0 top
NOREF#3031  -  []  215.38 193.86 90 top
NOREF#3032  -  []  230.5 243.67 90 top
NOREF#3033  -  []  461.75 217.95 0 top
NOREF#3034  -  []  266.74 294.64 0 top
NOREF#3035  -  []  308.57 184.96 0 top
NOREF#3036  -  []  355.91 223.58 0 top
NOREF#3037  -  []  294.66 252.79 0 top
NOREF#3038  -  []  116.04 253.35 0 top
NOREF#3039  -  []  306.54 133.3 90 top
NOREF#3040  -  []  308.66 226.14 0 top
NOREF#3041  -  []  280.48 209.12 0 top
NOREF#3042  -  []  352.45 243.7 90 top
NOREF#3043  -  []  90.79 209.32 0 top
NOREF#3044  -  []  215.16 251.22 90 top
NOREF#3045  -  []  268.93 241.38 0 top
NOREF#3046  -  []  270.84 182.62 0 top
NOREF#3047  -  []  303.95 174.38 90 top
NOREF#3048  -  []  543.62 154.21 90 top
NOREF#3049  -  []  261.62 289.14 90 top
NOREF#3050  -  []  236.65 267.92 90 top
NOREF#3051  -  []  335.38 193.86 90 top
NOREF#3052  -  []  456.64 202.18 90 top
NOREF#3053  -  []  276.37 207.56 0 top
NOREF#3054  -  []  480.18 171.07 0 top
NOREF#3055  -  []  214.36 253.12 0 top
NOREF#3056  -  []  541.61 164.49 0 top
NOREF#3057  -  []  308.01 173.3 90 top
NOREF#3058  -  []  363.98 267.75 0 top
NOREF#3059  -  []  335.01 182 90 top
NOREF#3060  -  []  231.48 191.08 0 top
